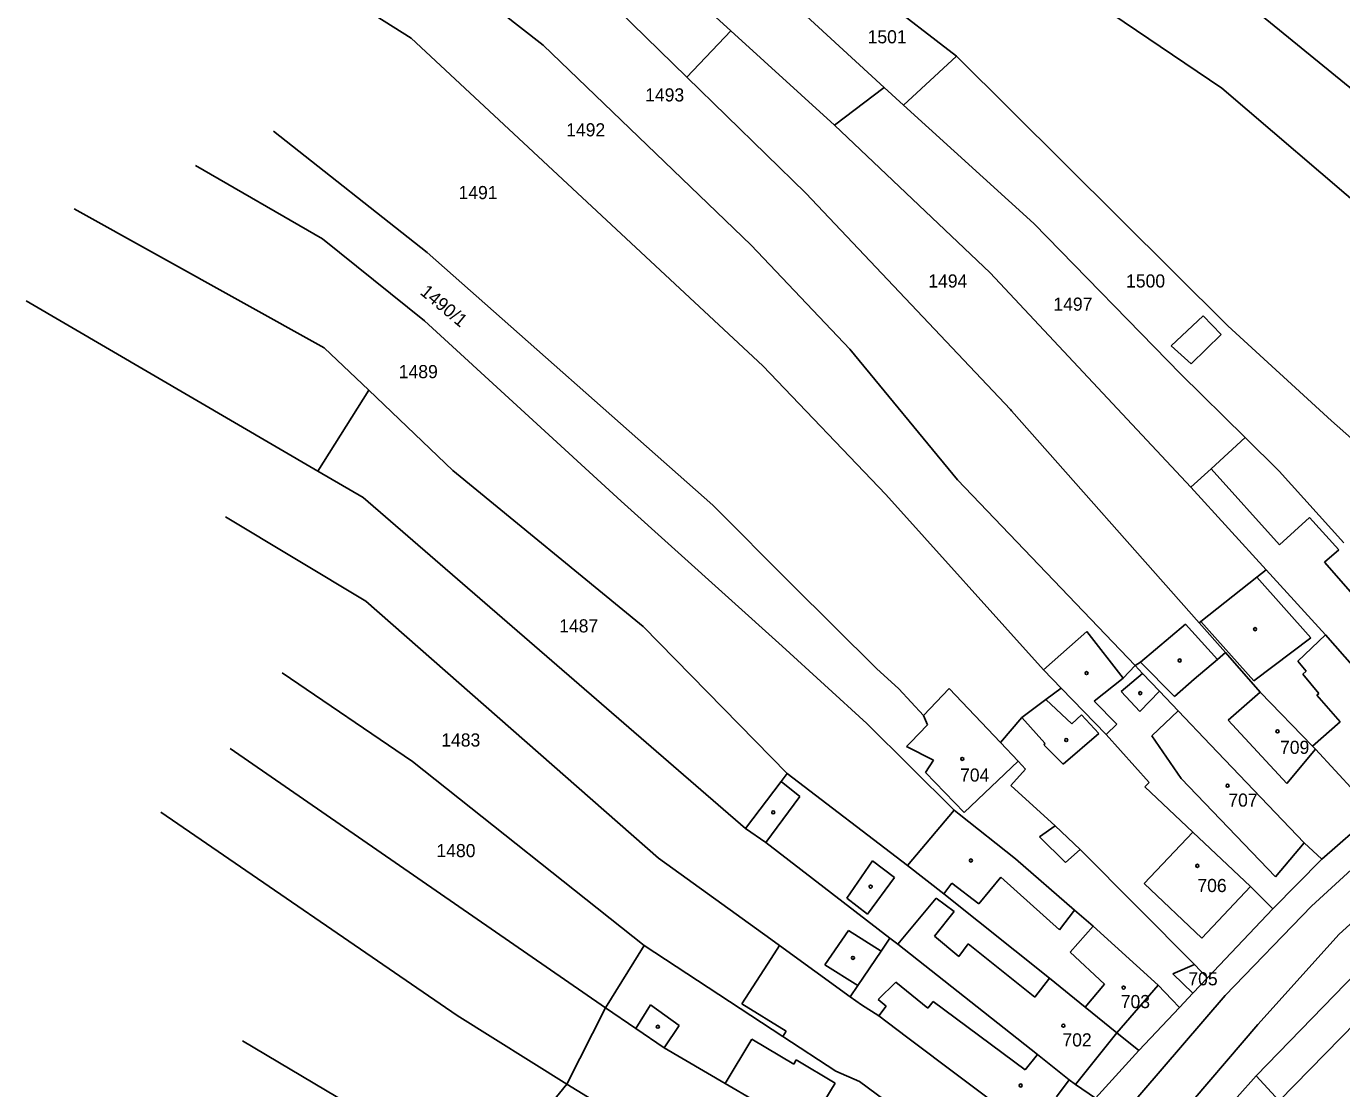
# Model space of a CAD drawing. Extents: x -563148 to -561712, y -1182311 to -1179502.
# Drawn here: x -562845.4 to -562695, y -1181163.6 to -1181042.2 of the extents above; entities that cross this region are included whole.
import ezdxf

# ---------------------------------------------------------------- set-up
doc = ezdxf.new("R2010")
doc.units = 0
for name, color, linetype in [('Vrstva 55', 7, 'Continuous'), ('Vrstva 56', 7, 'Continuous'), ('Vrstva 57', 7, 'Continuous')]:
    doc.layers.add(name, color=color, linetype=linetype)

msp = doc.modelspace()

# ---------------------------------------------------------------- linework, layer by layer
at = {"layer": 'Vrstva 55'}
for p, q in [((-562790.31, -1181019.57), (-562764.83, -1181042.76)), ((-562806.11, -1181028.89), (-562786.3, -1181044.4)), ((-562757.36, -1181031.48), (-562739.06, -1181045.65)), ((-562815.54, -1181034.63), (-562801.4, -1181043.61)), ((-562783.75, -1181034.5), (-562769.89, -1181048.04)), ((-562760.63, -1181036.95), (-562747.32, -1181049.24)), ((-562708.72, -1181049.31), (-562724.09, -1181038.86)), ((-562704.19, -1181040.99), (-562685.02, -1181056.64)), ((-562801.4, -1181043.61), (-562761.19, -1181081.05)), ((-562769.89, -1181048.04), (-562764.83, -1181042.76)), ((-562764.83, -1181042.76), (-562753, -1181053.53)), ((-562786.3, -1181044.4), (-562762.52, -1181067.24)), ((-562745.09, -1181051.26), (-562739.06, -1181045.65)), ((-562739.06, -1181045.65), (-562708.01, -1181076.45)), ((-562769.89, -1181048.04), (-562756.29, -1181061.31)), ((-562753, -1181053.53), (-562747.32, -1181049.24)), ((-562747.32, -1181049.24), (-562745.09, -1181051.26)), ((-562691.07, -1181064.4), (-562708.72, -1181049.31)), ((-562745.09, -1181051.26), (-562730.19, -1181064.77)), ((-562817.14, -1181054.23), (-562799.57, -1181068.1)), ((-562753, -1181053.53), (-562735.19, -1181070.43)), ((-562826.04, -1181058.13), (-562811.52, -1181066.54)), ((-562756.29, -1181061.31), (-562732.89, -1181086.02)), ((-562839.92, -1181063.11), (-562811.32, -1181079)), ((-562730.19, -1181064.77), (-562713.39, -1181081.98)), ((-562811.52, -1181066.54), (-562799.87, -1181075.9)), ((-562762.52, -1181067.24), (-562751.23, -1181079.12)), ((-562799.57, -1181068.1), (-562766.92, -1181096.95)), ((-562735.19, -1181070.43), (-562712.26, -1181094.9)), ((-562845.39, -1181073.62), (-562812.05, -1181093.06)), ((-562799.87, -1181075.9), (-562777.38, -1181096.49)), ((-562708.01, -1181076.45), (-562696.19, -1181087.31)), ((-562811.32, -1181079), (-562806.25, -1181083.82)), ((-562751.23, -1181079.12), (-562738.93, -1181094.06)), ((-562761.19, -1181081.05), (-562747.12, -1181095.73)), ((-562713.39, -1181081.98), (-562706.04, -1181089.23)), ((-562812.05, -1181093.06), (-562806.25, -1181083.82)), ((-562806.25, -1181083.82), (-562796.62, -1181092.99)), ((-562732.89, -1181086.02), (-562732.76, -1181086.19)), ((-562732.76, -1181086.19), (-562711.32, -1181110.41)), ((-562696.19, -1181087.31), (-562686.87, -1181095.58)), ((-562709.94, -1181092.79), (-562706.04, -1181089.23)), ((-562706.04, -1181089.23), (-562702.16, -1181093.06)), ((-562812.05, -1181093.06), (-562806.86, -1181096.08)), ((-562796.62, -1181092.99), (-562774.87, -1181110.82)), ((-562712.26, -1181094.9), (-562709.94, -1181092.79)), ((-562702.16, -1181093.06), (-562694.75, -1181101.26)), ((-562738.93, -1181094.06), (-562718.62, -1181115.3)), ((-562703.66, -1181104.34), (-562712.26, -1181094.9)), ((-562806.86, -1181096.08), (-562763.17, -1181133.92)), ((-562777.38, -1181096.49), (-562758.98, -1181113.07)), ((-562747.12, -1181095.73), (-562729.11, -1181115.78)), ((-562766.92, -1181096.95), (-562757.96, -1181105.95)), ((-562822.63, -1181098.3), (-562806.59, -1181107.94)), ((-562711.13, -1181110.26), (-562704.72, -1181105.17)), ((-562704.72, -1181105.17), (-562703.66, -1181104.34)), ((-562703.66, -1181104.34), (-562696.86, -1181111.79)), ((-562757.96, -1181105.95), (-562748.2, -1181115.61)), ((-562806.59, -1181107.94), (-562773.11, -1181137.31)), ((-562774.87, -1181110.82), (-562758.39, -1181127.62)), ((-562729.11, -1181115.78), (-562724.13, -1181111.41)), ((-562724.13, -1181111.41), (-562720, -1181116.71)), ((-562718, -1181114.91), (-562712.85, -1181110.56)), ((-562712.85, -1181110.56), (-562709.22, -1181114.6)), ((-562711.32, -1181110.41), (-562711.13, -1181110.26)), ((-562708.3, -1181113.81), (-562711.32, -1181110.41)), ((-562758.98, -1181113.07), (-562749.31, -1181121.92)), ((-562696.86, -1181111.79), (-562686.46, -1181123.63)), ((-562709.22, -1181114.6), (-562708.3, -1181113.81)), ((-562704.32, -1181118.31), (-562708.3, -1181113.81)), ((-562748.2, -1181115.61), (-562745.64, -1181117.95)), ((-562727.07, -1181117.88), (-562729.11, -1181115.78)), ((-562720, -1181116.71), (-562718.62, -1181115.3)), ((-562718.62, -1181115.3), (-562718, -1181114.91)), ((-562718.62, -1181115.3), (-562717.78, -1181116.18)), ((-562816.14, -1181116.13), (-562801.23, -1181126.24)), ((-562717.78, -1181116.18), (-562715.84, -1181118.22)), ((-562745.64, -1181117.95), (-562742.83, -1181121)), ((-562742.83, -1181121), (-562739.87, -1181117.92)), ((-562739.87, -1181117.92), (-562734.02, -1181124.08)), ((-562728.83, -1181119.18), (-562727.07, -1181117.88)), ((-562727.07, -1181117.88), (-562721.94, -1181123.16)), ((-562715.84, -1181118.22), (-562713.72, -1181120.45)), ((-562698.34, -1181124.51), (-562704.32, -1181118.31)), ((-562731.58, -1181121.23), (-562728.83, -1181119.18)), ((-562713.72, -1181120.45), (-562710, -1181124.35)), ((-562749.31, -1181121.92), (-562739.31, -1181131.8)), ((-562744.32, -1181124.08), (-562742.35, -1181122.07)), ((-562742.35, -1181122.07), (-562742.83, -1181121)), ((-562734.02, -1181124.08), (-562731.58, -1181121.23)), ((-562721.94, -1181123.16), (-562717.02, -1181128.66)), ((-562822.1, -1181124.75), (-562779.17, -1181154.4)), ((-562744.77, -1181124.54), (-562744.32, -1181124.08)), ((-562741.68, -1181126.08), (-562744.77, -1181124.54)), ((-562734.02, -1181124.08), (-562732.01, -1181126.2)), ((-562710, -1181124.35), (-562699.3, -1181135.55)), ((-562698.02, -1181124.86), (-562698.34, -1181124.51)), ((-562693.5, -1181129.73), (-562698.02, -1181124.86)), ((-562801.23, -1181126.24), (-562774.76, -1181147.26)), ((-562742.58, -1181127.49), (-562741.68, -1181126.08)), ((-562732.01, -1181126.2), (-562738.17, -1181132.08)), ((-562731.14, -1181127.12), (-562732.01, -1181126.2)), ((-562759.08, -1181128.53), (-562758.39, -1181127.62)), ((-562758.39, -1181127.62), (-562744.63, -1181138.12)), ((-562738.17, -1181132.08), (-562742.58, -1181127.49)), ((-562732.82, -1181129), (-562731.14, -1181127.12)), ((-562763.17, -1181133.92), (-562759.08, -1181128.53)), ((-562727.78, -1181133.62), (-562732.82, -1181129)), ((-562717.02, -1181128.66), (-562717.51, -1181129.13)), ((-562717.51, -1181129.13), (-562712.02, -1181134.32)), ((-562830.01, -1181132.03), (-562796.13, -1181155.26)), ((-562744.63, -1181138.12), (-562739.31, -1181131.8)), ((-562739.31, -1181131.8), (-562738.73, -1181132.26)), ((-562738.73, -1181132.26), (-562732.29, -1181137.39)), ((-562697.27, -1181137.42), (-562691.27, -1181132.16)), ((-562760.84, -1181135.52), (-562763.17, -1181133.92)), ((-562724.89, -1181136.32), (-562727.78, -1181133.62)), ((-562746.67, -1181146.43), (-562760.84, -1181135.52)), ((-562712.02, -1181134.32), (-562705.43, -1181140.55)), ((-562699.3, -1181135.55), (-562697.27, -1181137.42)), ((-562711.85, -1181149.45), (-562724.89, -1181136.32)), ((-562773.11, -1181137.31), (-562760.28, -1181146.54)), ((-562744.63, -1181138.12), (-562740.5, -1181141.36)), ((-562732.29, -1181137.39), (-562725.55, -1181143.24)), ((-562702.88, -1181143.09), (-562697.27, -1181137.42)), ((-562740.5, -1181141.36), (-562728.41, -1181151.01)), ((-562705.43, -1181140.55), (-562702.88, -1181143.09)), ((-562710.34, -1181150.97), (-562702.88, -1181143.09)), ((-562725.55, -1181143.24), (-562723.42, -1181145.08)), ((-562754.1, -1181149.47), (-562751.41, -1181145.56)), ((-562751.41, -1181145.56), (-562747.67, -1181147.92)), ((-562723.42, -1181145.08), (-562715.99, -1181151.82)), ((-562779.17, -1181154.4), (-562774.76, -1181147.26)), ((-562774.76, -1181147.26), (-562758.91, -1181157.67)), ((-562760.28, -1181146.54), (-562759.27, -1181147.28)), ((-562760.24, -1181148.78), (-562759.27, -1181147.28)), ((-562759.27, -1181147.28), (-562751.21, -1181153.13)), ((-562747.67, -1181147.92), (-562746.67, -1181146.43)), ((-562746.67, -1181146.43), (-562745.77, -1181147.11)), ((-562745.77, -1181147.11), (-562729.8, -1181159.73)), ((-562763.57, -1181153.95), (-562760.24, -1181148.78)), ((-562704.77, -1181162.16), (-562692.04, -1181149.02)), ((-562750.33, -1181151.84), (-562754.1, -1181149.47)), ((-562714.33, -1181150.53), (-562711.85, -1181149.45)), ((-562712.01, -1181152.73), (-562714.33, -1181150.53)), ((-562711.85, -1181149.45), (-562711.14, -1181150.16)), ((-562711.14, -1181150.16), (-562710.34, -1181150.97)), ((-562751.21, -1181153.13), (-562750.33, -1181151.84)), ((-562728.41, -1181151.01), (-562724.32, -1181154.33)), ((-562715.99, -1181151.82), (-562714.44, -1181153.44)), ((-562712.01, -1181152.73), (-562710.34, -1181150.97)), ((-562751.21, -1181153.13), (-562749.9, -1181154.07)), ((-562714.44, -1181153.44), (-562713.55, -1181154.36)), ((-562713.55, -1181154.36), (-562712.01, -1181152.73)), ((-562775.72, -1181156.75), (-562779.17, -1181154.4)), ((-562758.53, -1181157.07), (-562763.57, -1181153.95)), ((-562749.9, -1181154.07), (-562747.91, -1181155.32)), ((-562724.32, -1181154.33), (-562720.7, -1181157.26)), ((-562718.22, -1181159.28), (-562713.55, -1181154.36)), ((-562796.13, -1181155.26), (-562783.58, -1181163.12)), ((-562747.91, -1181155.32), (-562744.77, -1181157.73)), ((-562820.69, -1181158.16), (-562793.04, -1181174.54)), ((-562772.47, -1181158.97), (-562775.72, -1181156.75)), ((-562758.91, -1181157.67), (-562758.53, -1181157.07)), ((-562758.91, -1181157.67), (-562752.85, -1181161.64)), ((-562744.77, -1181157.73), (-562730.44, -1181168.46)), ((-562720.7, -1181157.26), (-562718.22, -1181159.28)), ((-562765.49, -1181163.06), (-562772.47, -1181158.97)), ((-562723.17, -1181164.72), (-562718.22, -1181159.28)), ((-562729.8, -1181159.73), (-562726.17, -1181162.62)), ((-562752.85, -1181161.64), (-562750.14, -1181162.82)), ((-562726.17, -1181162.62), (-562725.45, -1181163.17)), ((-562716.11, -1181174.8), (-562704.77, -1181162.16)), ((-562702.14, -1181165.02), (-562704.77, -1181162.16)), ((-562783.58, -1181163.12), (-562765.56, -1181174.13)), ((-562762.1, -1181165.04), (-562765.49, -1181163.06)), ((-562750.14, -1181162.82), (-562739.15, -1181170.88)), ((-562725.45, -1181163.17), (-562723.17, -1181164.72))]:
    msp.add_line(p, q, dxfattribs=at)
at = {"layer": 'Vrstva 56'}
for p, q in [((-562714.49, -1181078.74), (-562710.86, -1181075.32)), ((-562710.86, -1181075.32), (-562708.78, -1181077.44)), ((-562708.78, -1181077.44), (-562712.21, -1181080.82)), ((-562712.21, -1181080.82), (-562714.49, -1181078.74)), ((-562709.94, -1181092.79), (-562702.11, -1181101.48)), ((-562702.11, -1181101.48), (-562698.68, -1181098.37)), ((-562698.68, -1181098.37), (-562695.33, -1181102.07)), ((-562695.33, -1181102.07), (-562696.98, -1181103.47)), ((-562696.98, -1181103.47), (-562686.07, -1181115.95)), ((-562704.72, -1181105.17), (-562698.55, -1181112.12)), ((-562705.04, -1181117.04), (-562711.13, -1181110.26)), ((-562698.55, -1181112.12), (-562705.04, -1181117.04)), ((-562700.02, -1181114.78), (-562696.86, -1181111.79)), ((-562714.14, -1181118.82), (-562718, -1181114.91)), ((-562709.22, -1181114.6), (-562711.86, -1181116.86)), ((-562699.08, -1181115.93), (-562700.02, -1181114.78)), ((-562699.47, -1181116.29), (-562699.08, -1181115.93)), ((-562720, -1181116.71), (-562723.32, -1181119.36)), ((-562720.21, -1181118.26), (-562717.78, -1181116.18)), ((-562711.86, -1181116.86), (-562714.14, -1181118.82)), ((-562697.62, -1181118.47), (-562699.47, -1181116.29)), ((-562718.09, -1181120.52), (-562720.21, -1181118.26)), ((-562715.84, -1181118.22), (-562718.09, -1181120.52)), ((-562708, -1181121.53), (-562704.32, -1181118.31)), ((-562698.46, -1181142.78), (-562672.21, -1181118.66)), ((-562697.85, -1181118.67), (-562697.62, -1181118.47)), ((-562695.18, -1181121.7), (-562697.85, -1181118.67)), ((-562728.83, -1181119.18), (-562725.85, -1181121.96)), ((-562723.32, -1181119.36), (-562720.72, -1181121.98)), ((-562716.73, -1181123.31), (-562713.72, -1181120.45)), ((-562728.93, -1181124.17), (-562731.58, -1181121.23)), ((-562725.85, -1181121.96), (-562724.77, -1181120.91)), ((-562724.77, -1181120.91), (-562722.76, -1181123.04)), ((-562720.72, -1181121.98), (-562721.94, -1181123.16)), ((-562701.28, -1181128.75), (-562708, -1181121.53)), ((-562698.34, -1181124.51), (-562695.18, -1181121.7)), ((-562669.33, -1181122.11), (-562695.29, -1181145.99)), ((-562722.76, -1181123.04), (-562726.86, -1181126.57)), ((-562713.36, -1181128.21), (-562716.73, -1181123.31)), ((-562729.03, -1181124.39), (-562728.93, -1181124.17)), ((-562726.86, -1181126.57), (-562729.03, -1181124.39)), ((-562698.02, -1181124.86), (-562701.28, -1181128.75)), ((-562759.08, -1181128.53), (-562756.97, -1181130.24)), ((-562702.57, -1181139.42), (-562713.36, -1181128.21)), ((-562756.97, -1181130.24), (-562760.84, -1181135.52)), ((-562729.57, -1181134.85), (-562727.78, -1181133.62)), ((-562726.57, -1181137.78), (-562729.57, -1181134.85)), ((-562717.61, -1181140.18), (-562712.02, -1181134.32)), ((-562699.3, -1181135.55), (-562702.57, -1181139.42)), ((-562724.89, -1181136.32), (-562726.57, -1181137.78)), ((-562751.58, -1181141.87), (-562748.65, -1181137.62)), ((-562748.65, -1181137.62), (-562746.13, -1181139.49)), ((-562746.13, -1181139.49), (-562749.23, -1181143.68)), ((-562739.57, -1181140.15), (-562740.5, -1181141.36)), ((-562736.48, -1181142.53), (-562739.57, -1181140.15)), ((-562733.99, -1181139.48), (-562736.48, -1181142.53)), ((-562727.26, -1181145.48), (-562733.99, -1181139.48)), ((-562711.01, -1181146.43), (-562717.61, -1181140.18)), ((-562705.43, -1181140.55), (-562711.01, -1181146.43)), ((-562749.23, -1181143.68), (-562751.58, -1181141.87)), ((-562745.77, -1181147.11), (-562741.38, -1181141.87)), ((-562741.38, -1181141.87), (-562739.3, -1181143.38)), ((-562708.34, -1181152.98), (-562698.46, -1181142.78)), ((-562739.3, -1181143.38), (-562741.55, -1181146.2)), ((-562725.55, -1181143.24), (-562727.26, -1181145.48)), ((-562726.07, -1181148.05), (-562723.42, -1181145.08)), ((-562695.29, -1181145.99), (-562704.58, -1181156.31)), ((-562741.55, -1181146.2), (-562738.79, -1181148.55)), ((-562738.79, -1181148.55), (-562737.72, -1181147.1)), ((-562737.72, -1181147.1), (-562730.11, -1181153.19)), ((-562747.67, -1181147.92), (-562750.33, -1181151.84)), ((-562722.12, -1181151.7), (-562726.07, -1181148.05)), ((-562748.01, -1181153.44), (-562745.99, -1181151.48)), ((-562745.99, -1181151.48), (-562742.33, -1181154.43)), ((-562730.11, -1181153.19), (-562728.41, -1181151.01)), ((-562724.32, -1181154.33), (-562722.12, -1181151.7)), ((-562715.99, -1181151.82), (-562720.7, -1181157.26)), ((-562747.07, -1181154.21), (-562748.01, -1181153.44)), ((-562742.33, -1181154.43), (-562741.7, -1181153.66)), ((-562741.7, -1181153.66), (-562731.19, -1181161.49)), ((-562726.78, -1181174.46), (-562708.34, -1181152.98)), ((-562783.58, -1181163.12), (-562779.17, -1181154.4)), ((-562775.72, -1181156.75), (-562774.03, -1181154.05)), ((-562774.03, -1181154.05), (-562770.76, -1181156.41)), ((-562747.91, -1181155.32), (-562747.07, -1181154.21)), ((-562702.14, -1181165.02), (-562691.57, -1181154.2)), ((-562770.76, -1181156.41), (-562772.47, -1181158.97)), ((-562704.58, -1181156.31), (-562722.81, -1181177.55)), ((-562765.49, -1181163.06), (-562762.46, -1181157.97)), ((-562762.46, -1181157.97), (-562757.66, -1181160.82)), ((-562720.7, -1181157.26), (-562725.45, -1181163.17)), ((-562757.66, -1181160.82), (-562757.38, -1181160.35)), ((-562757.38, -1181160.35), (-562752.91, -1181163.01)), ((-562731.19, -1181161.49), (-562729.8, -1181159.73)), ((-562726.17, -1181162.62), (-562727.61, -1181164.58)), ((-562793.04, -1181174.54), (-562783.58, -1181163.12)), ((-562752.91, -1181163.01), (-562754.11, -1181164.95))]:
    msp.add_line(p, q, dxfattribs=at)
at = {"layer": 'Vrstva 57'}
for centre in [(-562704.91, -1181111.13), (-562713.53, -1181114.71), (-562724.18, -1181116.15), (-562718.04, -1181118.44), (-562702.35, -1181122.81), (-562726.5, -1181123.8), (-562738.38, -1181125.95), (-562708.06, -1181129.02), (-562760, -1181132.06), (-562737.4, -1181137.56), (-562711.51, -1181138.17), (-562748.86, -1181140.55), (-562750.88, -1181148.69), (-562719.94, -1181152.09), (-562773.19, -1181156.56), (-562726.83, -1181156.44), (-562731.71, -1181163.27)]:
    msp.add_circle(centre, 0.175, dxfattribs=at)

# ---------------------------------------------------------------- texts
for s, p in [('1501', (-562749.21, -1181044.19)), ('1493', (-562774.64, -1181050.83)), ('1492', (-562783.67, -1181054.82)), ('1491', (-562795.98, -1181061.99)), ('1494', (-562742.27, -1181072.09)), ('1500', (-562719.66, -1181072.09)), ('1497', (-562727.97, -1181074.74)), ('1489', (-562802.81, -1181082.45)), ('1487', (-562784.47, -1181111.5)), ('1483', (-562797.95, -1181124.54)), ('709', (-562702.06, -1181125.38)), ('704', (-562738.64, -1181128.55)), ('707', (-562707.97, -1181131.41)), ('1480', (-562798.5, -1181137.18)), ('706', (-562711.51, -1181141.17)), ('705', (-562712.54, -1181151.83)), ('703', (-562720.27, -1181154.43)), ('702', (-562726.94, -1181158.81))]:
    msp.add_text(s, height=1.5, dxfattribs=at).set_placement(p)
msp.add_text('1490/1', height=1.5, rotation=320.1042, dxfattribs=at).set_placement((-562800.47, -1181072.78))

doc.saveas('drawing.dxf')
